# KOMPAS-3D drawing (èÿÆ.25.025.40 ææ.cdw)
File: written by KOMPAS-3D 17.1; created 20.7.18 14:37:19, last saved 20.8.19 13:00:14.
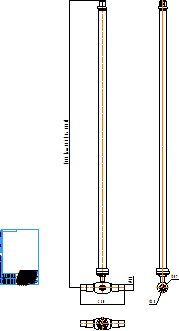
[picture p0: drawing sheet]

Sheet 1: A4, portrait

Title block, sheet 1: name: КШТ.25.025.40 С/С; sheets: 1; sheet format: A4; stored path: C:\Users\kka\KOMPAS_Work\Модели кранов для исследований\DN32\С удлинением\КШТ.22.032.40 СС.cdw

Views: Вид 1, Проекционный вид 2, Проекционный вид 3
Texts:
  kka
  adl
  (от 203,1 до 5000)
  Рама для чертежей
  Лит-Масса-Масштаб
  Материал-Предприятие
  Масштаб
  Изм.
  Лист
  № докум.
  Подп.
  Дата
  Лит.
  Разраб.
  Пров.
  Т.контр.
  Листов
  Внимание! Данный продукт является объектом авторского права ООО «Торговый Дом АДЛ».
  Запрещается изменение, копирование, распространение
  (в том числе путем копирования на другие сайты и ресурсы в Интернете)
  или любое иное использование информации и объектов без предварительного
  согласия правообладателя (ООО «Торговый Дом АДЛ»).
  Н.контр.
  Утв.
  ООО "Торговый дом АДЛ"
  Изменение
  Номер документа
  Подпись
  Обозначение документа
  Наименование изделия
  Масса изделия по ГОСТ 2.109-73
  Порядковый номер листа
  Общее количество листов в документе
  Характер работы, выполненной лицом, подписавшим документ
  Наименование или индекс предприятия, выпускающего документ
  Инв. № подл.
  Подп. и дата
  Взам. инв. №
  Инв. № дубл.
  Инвентарный номер подлинника по ГОСТ 2.501-68
  Подпись принявшего подлинник в отдел технической документации
  Инвентарный номер подлинника, взамен которого выпущен данный подлинник
  Инвентарный номер дубликата по ГОСТ 2.502-68
  Подпись принявшего дубликат в отдел технической документации
  Справ. №
  Перв. примен.
  Обозначение документа, взамен или на основании которого выпущен данный документ
  Обозначение документа, в котором впервые записан данный документ
  Подпись лица, копировавшего чертеж
  Обозначение формата листа
  !Рама для чертежа
Dimensions and other numbers on the sheet: 1500; 230; 32; 57; 25; 1:1; 1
